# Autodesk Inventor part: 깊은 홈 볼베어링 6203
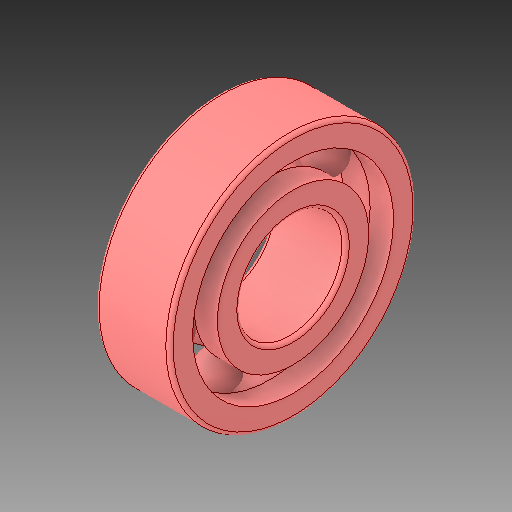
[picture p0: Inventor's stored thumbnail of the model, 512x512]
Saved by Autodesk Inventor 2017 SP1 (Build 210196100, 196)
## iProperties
Created: 2024-09
Part Number: 깊은 홈 볼베어링 6203
Material: 일반
Description: 깊은 그루브 볼 베어링
Document SubType Name: Modeling
Designer: MRC
Density: 1 g/cm^3
Appearance: 기본값
Author: jhkim
Sending System: Autodesk Inventor 2025
Preprocessor: ST-DEVELOPER v20
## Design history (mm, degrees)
feature "Solid1"
feature "Solid1:1"
feature "Solid1:2"
feature "Solid1:3"
feature "Solid1:4"
feature "Solid1:5"
feature "Solid1:6"
feature "Solid1:7"
feature "Solid1:8"
node "솔리드1"
node "솔리드2"
node "솔리드3"
node "솔리드4"
node "솔리드5"
node "솔리드6"
node "솔리드7"
node "솔리드8"
node "솔리드9"
